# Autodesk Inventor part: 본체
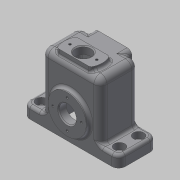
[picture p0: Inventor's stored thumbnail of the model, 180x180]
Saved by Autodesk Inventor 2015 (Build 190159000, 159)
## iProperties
Created: 2023-12
Part Number: 본체
Material: 일반
Document SubType Name: Modeling
Designer: 10415
Density: 1 g/cm^3
Appearance: 기본값
Author: 10415
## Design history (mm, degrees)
sketch "스케치1"
  geometry: L1 (31, 20)-(-31, 20); L2 (-31, 20)-(-31, -20); L3 (-31, -20)-(31, -20); L4 (31, -20)-(31, 20); L5 (31, 20)-(-31, -20); L6 (-31, 20)-(31, -20); 1 further point
  constraints: 12 end point, 2 midpoint, 2 parallel, 1 horizontal, 1 perpendicular
  dimensions: "d0" = 62 distance of L2.end L3.end; "d1" = 40 distance of L1.end L2.end
extrude "돌출1" new body sketch "스케치1" distance "d2" = 72; taper "d3" = 0 deg
fillet "모깎기1" dims "d8" = 7
fillet "모깎기2" dims "d9" = 7
feature "쉘1" dims "d10" = 4
sketch "스케치3"
  geometry: L1 (50, -20)-(-50, -20); L2 (-50, -20)-(-50, 20); L3 (-50, 20)-(50, 20); L4 (50, 20)-(50, -20); L5 (50, -20)-(-50, 20); L6 (-50, -20)-(50, 20); L7 (27, -13)-(27, 13) reference; L8 (24, 16)-(-24, 16) reference; L9 (-27, 13)-(-27, -13) reference; L10 (-24, -16)-(24, -16) reference; L11 (-24, -20)-(24, -20) reference; L12 (-31, 13)-(-31, -13) reference; L13 (24, 20)-(-24, 20) reference; L14 (31, -13)-(31, 13) reference; A1 r 3 centre (24, -13) between (24, -16) and (27, -13) reference; A2 r 3 centre (24, 13) between (27, 13) and (24, 16) reference; A3 r 3 centre (-24, 13) between (-24, 16) and (-27, 13) reference; A4 r 3 centre (-24, -13) between (-27, -13) and (-24, -16) reference; A5 r 7 centre (24, -13) between (24, -20) and (31, -13) reference; A6 r 7 centre (-24, -13) between (-31, -13) and (-24, -20) reference; A7 r 7 centre (-24, 13) between (-24, 20) and (-31, 13) reference; A8 r 7 centre (24, 13) between (31, 13) and (24, 20) reference; 1 further point
  constraints: 12 end point, 2 midpoint, 2 parallel, 1 horizontal, 1 perpendicular
  dimensions: "d11" = 100 distance of L2.end L3.end; "d12" = 40 distance of L1.end L2.end
extrude "돌출3" join sketch "스케치3" distance "d13" = 12; taper "d14" = 0 deg
fillet "모깎기3" dims "d15" = 7
sketch "스케치4"
  geometry: L1 (-24, 20)-(-43, 20) reference; 3 further points
  constraints: 1 vertical alignment
  dimensions: "d16" = 10 distance from line of L1 point (-41, 10); "d17" = 20 distance of point (-41, 10) point (-41, -10); "d18" = 41 horizontal distance of point (0, 0) point (-41, 10)
hole "구멍1" sketch "스케치4" at (-41, 10), (-41, -10) diameter "d19" = 6.6; stored, may be unused: countersink angle "d23" = 90 deg, drill point angle "d25" = 118 deg; dims "d20" = 6, "d21" = 11, "d22" = 6.6, "d24" = 8
sketch "스케치5"
  geometry: L1 (67, -65)-(-19, -65) reference; C1 r 20 at (24, -37); 2 further points
  constraints: 1 centre point, 1 midpoint, 1 vertical alignment
  dimensions: "d26" = 28 distance of point (24, -65) C1.centre; "d36" = 40 diameter of C1
extrude "돌출4" join sketch "스케치5" distance "d27" = 4; taper "d28" = 0 deg
sketch "스케치6"
  geometry: C1 r 20 at (0, 0) reference; C2 r 9 at (0, 0); 1 further point
  constraints: 1 centre point, 1 coincident
  dimensions: "d29" = 18 diameter of C2
extrude "돌출5" cut sketch "스케치6" distance "d30" = 10; taper "d31" = 0 deg
chamfer "모따기1" distance "d32" = 1; stored, may be unused: second distance "d33" = 2, angle "d34" = 45 deg
sketch "스케치7"
  geometry: C1 r 20 at (0, 0) reference; 2 further points
  constraints: 1 vertical alignment
  dimensions: "d35" = 15 distance of C1.centre point (0, 15)
hole "구멍2" sketch "스케치7" at (0, 15) diameter "d37" = 2.459; stored, may be unused: countersink angle "d41" = 90 deg, drill point angle "d43" = 118 deg; dims "d38" = 6, "d39" = 11, "d40" = 6.6, "d42" = 10
sketch "스케치8"
  geometry: L1 (-19, -65)-(67, -65) reference; C1 r 12 at (24, -37); 2 further points
  constraints: 1 centre point, 1 midpoint, 1 vertical alignment
  dimensions: "d47" = 28 distance of point (24, -65) C1.centre; "d48" = 24 diameter of C1
extrude "돌출6" join sketch "스케치8" distance "d49" = 4; taper "d50" = 0 deg
sketch "스케치9"
  geometry: C1 r 12 at (0, 0) reference; 1 further point
hole "구멍3" sketch "스케치9" at (0, 0) diameter "d51" = 13.835; stored, may be unused: countersink angle "d55" = 90 deg, drill point angle "d57" = 118 deg; dims "d52" = 32, "d53" = 11, "d54" = 6.6, "d56" = 10
sketch "스케치10"
  geometry: L1 (-19, -65)-(67, -65) reference; L2 (4, -17)-(44, -17); L3 (44, -17)-(44, 7); L4 (44, 7)-(4, 7); L5 (4, 7)-(4, -17); L6 (4, -17)-(44, 7); L7 (44, -17)-(4, 7); L8 (48, 7)-(0, 7) reference; 5 further points
  constraints: 12 end point, 6 midpoint, 2 parallel, 1 horizontal, 1 perpendicular, 1 vertical alignment
  dimensions: "d58" = 40 distance of L3.end L4.end; "d59" = 24 distance of L2.end L3.end
extrude "돌출7" join sketch "스케치10" distance "d60" = 4; taper "d62" = 0 deg; dims "d61" = 4, "d63" = 0
sketch "스케치11"
  geometry: L1 (44, 7)-(4, 7) reference; 3 further points
  constraints: 1 horizontal alignment
  dimensions: "d64" = 28 distance of point (10, 1) point (38, 1); "d65" = 6 distance from line of L1 point (10, 1); "d66" = 14 horizontal distance of point (24, -65) point (10, 1)
hole "구멍4" sketch "스케치11" at (10, 1), (38, 1) diameter "d67" = 2.459; stored, may be unused: countersink angle "d71" = 90 deg, drill point angle "d73" = 118 deg; dims "d68" = 6, "d69" = 11, "d70" = 6.6, "d72" = 10
sketch "스케치12"
  geometry: L1 (40, -8)-(0, -8) reference; L2 (0, -4)-(40, -4); L3 (40, -4)-(40, -12); L4 (40, -12)-(0, -12); L5 (0, -12)-(0, -4); L6 (0, -4)-(40, -12); L7 (40, -4)-(0, -12); 2 further points
  constraints: 12 end point, 3 midpoint, 2 parallel, 1 horizontal, 1 perpendicular
  dimensions: "d74" = 8 distance of L2.end L3.end
extrude "돌출8" join sketch "스케치12" distance "d75" = 4; taper "d76" = 0 deg
fillet "모깎기4" dims "d77" = 5
sketch "스케치13"
  geometry: L1 (-15, 24)-(15, 24) reference; L2 (21, 3)-(-21, 3); L3 (-21, 3)-(-21, -17); L4 (-21, -17)-(21, -17); L5 (21, -17)-(21, 3); L6 (21, 3)-(-21, -17); L7 (-21, 3)-(21, -17); A1 r 20 centre (0, -7) between (17.321, -17) and (17.321, 3); A2 r 20 centre (0, -7) between (-17.321, 3) and (-17.321, -17); 4 further points
  constraints: 12 end point, 4 midpoint, 4 point on circle, 4 point on line, 2 centre point, 2 parallel, 2 vertical alignment, 1 coincident, 1 horizontal, 1 perpendicular
  dimensions: "d79" = 31 distance from line of L1 A1.centre; "d80" = 20 distance of L2.end L3.end; "d81" = 42 distance of L3.end L4.end; "d82" = 20 radius of A2; "d83" = 20 radius of A1
extrude "돌출9" join sketch "스케치13" distance "d84" = 4; taper "d85" = 0 deg; dims "d101" = 4, "d102" = 0
sketch "스케치14"
  geometry: C1 r 8 at (0, -7); A1 r 20 centre (0, -7) between (-17.321, 3) and (-17.321, -17) reference; 1 further point
  constraints: 1 centre point, 1 coincident
  dimensions: "d86" = 16 diameter of C1
extrude "돌출10" cut sketch "스케치14" distance "d87" = 10; taper "d88" = 0 deg
sketch "스케치15"
  geometry: C1 r 8 at (0, -7) reference; 3 further points
  constraints: 2 horizontal alignment
  dimensions: "d89" = 28 distance of point (14, -7) point (-14, -7); "d90" = 14 distance of C1.centre point (-14, -7)
hole "구멍5" sketch "스케치15" at (-14, -7), (14, -7) diameter "d91" = 2.459; stored, may be unused: countersink angle "d95" = 90 deg, drill point angle "d97" = 118 deg; dims "d92" = 6, "d93" = 11, "d94" = 6.6, "d96" = 10
chamfer "모따기2" distance "d98" = 1; stored, may be unused: second distance "d99" = 2, angle "d100" = 45 deg
fillet "모깎기5" dims "d103" = 3
fillet "모깎기6" dims "d104" = 3
fillet "모깎기7" dims "d105" = 3
fillet "모깎기8" dims "d106" = 3
fillet "모깎기9" dims "d107" = 3
fillet "모깎기10" dims "d108" = 3
sketch "스케치16"
  geometry: L1 (26, -65)-(0, -65) reference; L2 (-11, -25)-(-11, -49) reference; 2 further points
  constraints: 1 other
  dimensions: "d109" = 40 distance from line of L1 point (12, -25); "d110" = 23 distance from line of L2 point (12, -25)
feature "엠보싱1" sketch "스케치16" dims "d111" = 0.5, "d112" = 0
node "솔리드1"
mirror "대칭1"
pattern_circular "원형 패턴1" dims angle "d45" = 360 deg
node "투영된 루프1"
